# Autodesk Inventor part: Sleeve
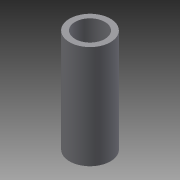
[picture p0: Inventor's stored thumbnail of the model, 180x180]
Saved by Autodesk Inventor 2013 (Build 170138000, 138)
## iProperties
Created: 2004-07
Part Number: Sleeve
Document SubType Name: Modeling
Designer: Autodesk, Inc.
Manufacturer: Standard
Standards Organization: Custom
Density: 1 g/cm^3
Mass: 9.93843 g
Surface Area: 69.8376 cm^2
Volume: 9.93843 cm^3
Material: Generic
Author: Autodesk, Inc.
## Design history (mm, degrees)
sketch "Sketch1"
  geometry: C1 r 11 at (0, 0); C2 r 8 at (0, 0); 1 further point
  constraints: 2 centre point, 2 coincident
  dimensions: "d0" = 22 diameter of C1; "d1" = 16 diameter of C2
extrude "Extrusion1" new body sketch "Sketch1" distance "d2" = 55.5; taper "d3" = 0 deg
body "Solid1"
